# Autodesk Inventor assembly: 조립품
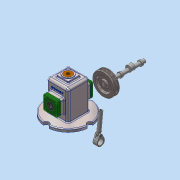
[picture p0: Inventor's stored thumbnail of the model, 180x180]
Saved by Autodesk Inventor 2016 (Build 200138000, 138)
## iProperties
Created: 2018-07
Part Number: 조립품
Material: 일반
Document SubType Name: Assembly
Designer: 605-17
Author: 605-17
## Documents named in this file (14)
- C:\480707V1014\조립품.iam
- C:\480707V1014\본체.ipt
- C:\480707V1014\뒤커버.ipt
- C:\480707V1014\앞커버.ipt
- C:\480707V1014\오일 실 12 25 7.ipt
- C:\480707V1014\베어링 12x32x10.ipt
- C:\480707V1014\고정핀 1.2x8.ipt
- C:\480707V1014\링크.ipt
- C:\480707V1014\슬라이드.ipt
- C:\480707V1014\핀 5x18.ipt
- C:\480707V1014\V벨트풀리.ipt
- C:\480707V1014\부시.ipt
- C:\480707V1014\편심축.ipt
- C:\480707V1014\키 4x4x10.ipt
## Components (3 placed, 3 different names)
1. 고정핀 1.2x8:1
2. 핀 5x18:1
3. V벨트풀리:1 — 각도:2
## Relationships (1: Angle 1)
- 각도:2 [Angle]: V벨트풀리:1
